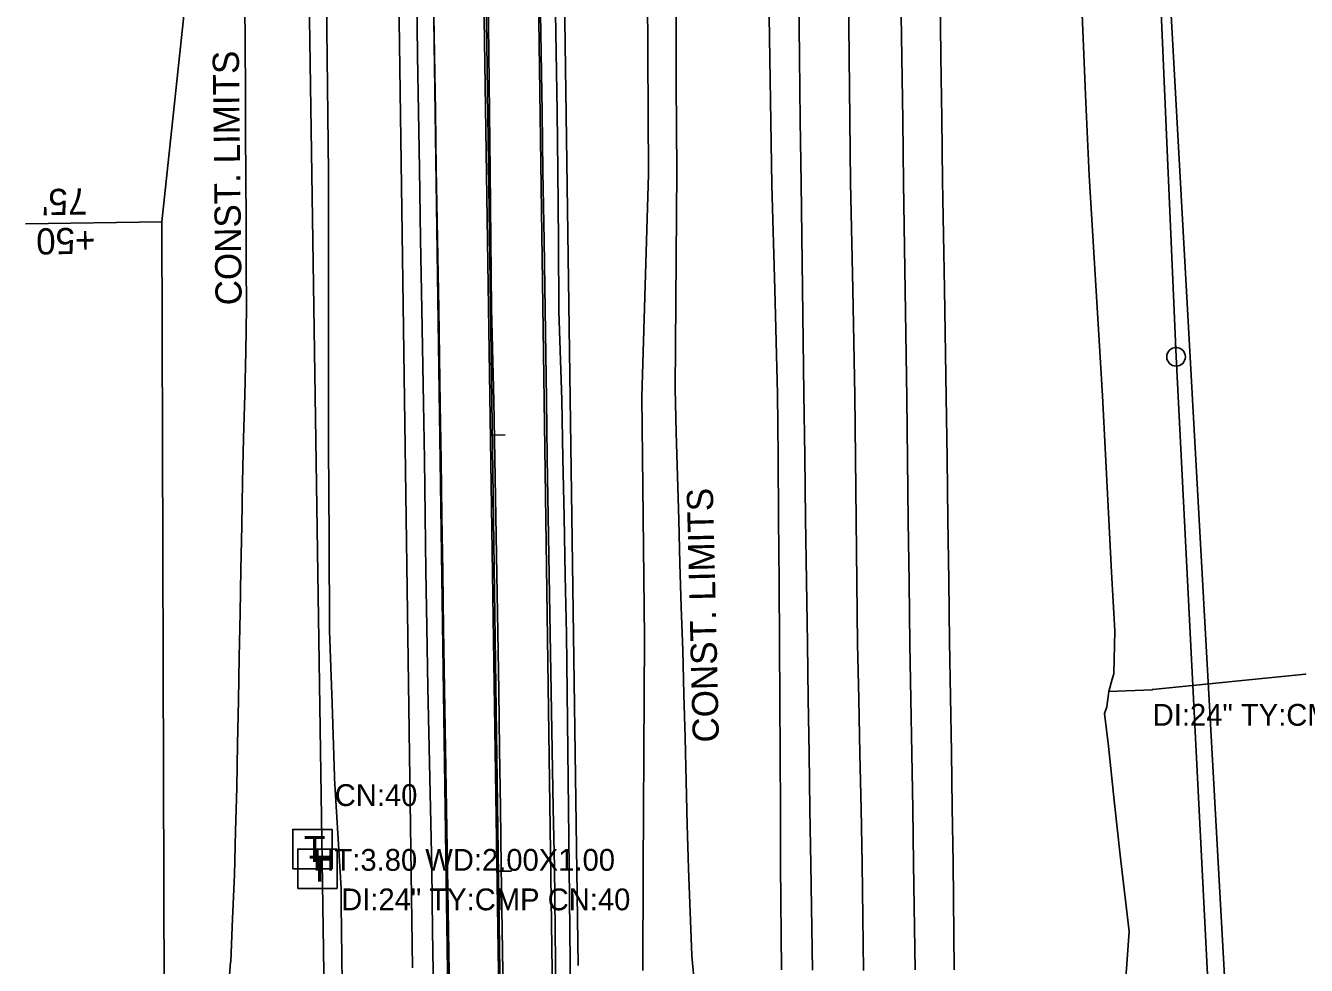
# Model space of a CAD drawing. Extents: x 1674300 to 1677920, y 225056 to 231852.
# Drawn here: x 1677262.1 to 1677555.6, y 229456.1 to 229671.6 of the extents above; entities that cross this region are included whole.
import ezdxf

# ---------------------------------------------------------------- set-up
doc = ezdxf.new("R2010")
doc.units = 0
for name, color, linetype in [('R_Annotation', 7, 'Continuous'), ('R_Horz Alg', 7, 'Continuous'), ('R_Horz Alg Annot', 7, 'Continuous'), ('R_Proposed Const Limits_Cut', 7, 'Continuous'), ('R_Proposed Const Limits_Fill', 7, 'Continuous'), ('R_Proposed Road_Lane', 7, 'Continuous'), ('R_Proposed Road_Shoulder', 7, 'Continuous'), ('R_ROW', 7, 'Continuous'), ('R_ROW Annot', 7, 'Continuous'), ('S_DITCHLINE', 7, 'Continuous'), ('S_DRG_PT_SYM', 7, 'Continuous'), ('S_EDGE_PAVEMENT', 7, 'Continuous'), ('S_ELECTRIC_UTILITIES', 7, 'Continuous'), ('S_EXIST_ROW', 7, 'Continuous'), ('S_EXISTING_ALIGNMENT', 7, 'Continuous'), ('S_PAVEMENT_CROWN', 7, 'Continuous'), ('S_SHOULDER', 7, 'Continuous'), ('S_SIDE_DRAIN', 7, 'Continuous'), ('S_SIDE_DRAIN_ANNOT', 7, 'Continuous'), ('S_TELEPHONE_UTILITIES', 7, 'Continuous'), ('S_TELEPHONE_UTILITIES_ANNOT', 7, 'Continuous'), ('S_UTILITY_POLE', 7, 'Continuous'), ('S_UTL_PT_SYM', 7, 'Continuous')]:
    doc.layers.add(name, color=color, linetype=linetype)

msp = doc.modelspace()

# ---------------------------------------------------------------- linework, layer by layer
at = {"layer": 'R_Horz Alg'}
msp.add_line((1677377.01, 229008.91), (1677360.58, 230177.65), dxfattribs=at)
at = {"layer": 'R_Horz Alg Annot'}
for points in [[(1677372.02, 229577.75), (1677369.02, 229577.71)], [(1677373.42, 229477.76), (1677370.42, 229477.72)]]:
    msp.add_lwpolyline(points, dxfattribs=at)
at = {"layer": 'R_Proposed Const Limits_Cut'}
msp.add_lwpolyline([(1677308.24, 229446.84), (1677309.07, 229456.86), (1677309.08, 229457.01), (1677309.52, 229466.86), (1677309.96, 229476.87), (1677310.21, 229486.88), (1677310.45, 229496.88), (1677310.66, 229506.88), (1677310.85, 229516.89), (1677311.03, 229526.89), (1677311.22, 229536.9), (1677311.43, 229546.9), (1677311.65, 229556.9), (1677311.82, 229566.91), (1677312.04, 229576.91), (1677312.3, 229586.92), (1677312.52, 229596.92), (1677312.7, 229606.92), (1677312.66, 229616.92), (1677312.6, 229626.92), (1677312.54, 229636.92), (1677312.5, 229646.92), (1677312.44, 229656.92), (1677312.36, 229666.92), (1677312.35, 229676.93)], dxfattribs=at)
at = {"layer": 'R_Proposed Const Limits_Fill'}
msp.add_lwpolyline([(1677415.72, 229448.36), (1677414.81, 229458.34), (1677414.79, 229458.49), (1677414.36, 229468.34), (1677414, 229478.33), (1677413.69, 229488.33), (1677413.49, 229498.33), (1677413.23, 229508.33), (1677412.94, 229518.32), (1677412.71, 229528.32), (1677412.35, 229538.32), (1677412.03, 229548.31), (1677411.76, 229558.31), (1677411.46, 229568.31), (1677411.18, 229578.3), (1677410.99, 229588.3), (1677411.04, 229598.3), (1677411.08, 229608.31), (1677411.17, 229618.31), (1677411.24, 229628.31), (1677411.31, 229638.31), (1677411.25, 229648.31), (1677411.21, 229658.31), (1677411.19, 229668.31), (1677411.16, 229678.31)], dxfattribs=at)
at = {"layer": 'R_Proposed Road_Lane'}
for p, q in [((1677362.08, 229217.16), (1677355.47, 229687.53)), ((1677386.08, 229217.34), (1677379.47, 229687.87))]:
    msp.add_line(p, q, dxfattribs=at)
at = {"layer": 'R_Proposed Road_Shoulder'}
for p, q in [((1677350.73, 229455.59), (1677347.47, 229687.42)), ((1677388.73, 229456.13), (1677385.47, 229687.95))]:
    msp.add_line(p, q, dxfattribs=at)
at = {"layer": 'R_ROW'}
for p, q in [((1677293.32, 229626.65), (1677323.6, 229911.16)), ((1677294.58, 229181.63), (1677293.32, 229626.65))]:
    msp.add_line(p, q, dxfattribs=at)
at = {"layer": 'R_ROW Annot'}
msp.add_line((1677293.32, 229626.65), (1677262.08, 229626.13), dxfattribs=at)
at = {"layer": 'S_DITCHLINE'}
for points in [[(1677332.94, 229497.27), (1677332.9, 229499.42), (1677332.33, 229516.14), (1677331.76, 229532.86), (1677331.63, 229554.02), (1677331.51, 229575.18), (1677331.5, 229590.35), (1677331.5, 229605.52), (1677331.51, 229621.71), (1677331.52, 229637.89), (1677331.37, 229651.06), (1677331.21, 229664.23), (1677331.06, 229677.4)], [(1677403.55, 229454.93), (1677403.6, 229478.23), (1677403.68, 229491.49), (1677403.77, 229504.75), (1677403.86, 229518.01), (1677403.95, 229531.26), (1677403.8, 229545.08), (1677403.64, 229558.9), (1677403.48, 229572.71), (1677403.33, 229586.53), (1677403.71, 229599.28), (1677404.09, 229612.04), (1677404.47, 229624.8), (1677404.85, 229637.56), (1677404.78, 229651.36), (1677404.72, 229665.16), (1677404.65, 229678.97)], [(1677513.78, 229446.92), (1677515.05, 229463.87), (1677512.97, 229481.43), (1677511.61, 229493.9), (1677510.26, 229506.37), (1677509.37, 229513.91), (1677509.86, 229515.44), (1677510.34, 229518.94), (1677511.09, 229521.77), (1677511.46, 229522.98), (1677511.69, 229532.84), (1677510.98, 229546.32), (1677510.28, 229559.79), (1677509.58, 229573.27), (1677508.88, 229586.74), (1677508.12, 229599.38), (1677507.36, 229612.01), (1677506.6, 229624.64), (1677505.84, 229637.27), (1677505.04, 229655.77), (1677504.24, 229674.27)], [(1677510.34, 229518.94), (1677520.35, 229519.32)], [(1677339.09, 229147.6), (1677337.05, 229154.23), (1677340.76, 229158.8), (1677340.29, 229166.32), (1677337.9, 229173.01), (1677337.54, 229184.7), (1677337.47, 229206.29), (1677336.46, 229228.55), (1677335.46, 229250.81), (1677335.75, 229270.19), (1677336.05, 229289.58), (1677334.99, 229313.98), (1677333.93, 229338.37), (1677333.99, 229360.23), (1677334.04, 229382.08), (1677334.5, 229402.19), (1677334.96, 229422.29), (1677334.69, 229446.15), (1677334.41, 229470.02), (1677334.41, 229473.73)]]:
    msp.add_lwpolyline(points, dxfattribs=at)
at = {"layer": 'S_DRG_PT_SYM'}
for points in [[(1677555.42, 229522.92), (1677555.42, 229522.97), (1677555.42, 229522.92), (1677555.37, 229522.92), (1677555.42, 229522.92), (1677555.42, 229522.87), (1677555.42, 229522.92), (1677555.47, 229522.92)], [(1677520.36, 229519.36), (1677520.36, 229519.41), (1677520.36, 229519.36), (1677520.31, 229519.36), (1677520.36, 229519.36), (1677520.36, 229519.31), (1677520.36, 229519.36), (1677520.41, 229519.36)], [(1677332.92, 229497.67), (1677332.92, 229497.72), (1677332.92, 229497.67), (1677332.87, 229497.67), (1677332.92, 229497.67), (1677332.92, 229497.62), (1677332.92, 229497.67), (1677332.97, 229497.67)], [(1677334.4, 229473.76), (1677334.4, 229473.81), (1677334.4, 229473.76), (1677334.35, 229473.76), (1677334.4, 229473.76), (1677334.4, 229473.71), (1677334.4, 229473.76), (1677334.45, 229473.76)]]:
    msp.add_lwpolyline(points, dxfattribs=at)
at = {"layer": 'S_EDGE_PAVEMENT'}
for points in [[(1677359.23, 229449.72), (1677359, 229463.99), (1677358.76, 229478.26), (1677358.53, 229492.04), (1677358.31, 229505.82), (1677358.08, 229519.61), (1677357.86, 229533.39), (1677357.67, 229546.25), (1677357.48, 229559.11), (1677357.29, 229571.97), (1677357.1, 229584.84), (1677356.8, 229606.58), (1677356.5, 229622.72), (1677356.2, 229638.87), (1677355.99, 229651.98), (1677355.78, 229665.09), (1677355.57, 229678.21)], [(1677383.6, 229449.7), (1677383.44, 229464.22), (1677383.27, 229478.73), (1677383.02, 229492.11), (1677382.77, 229505.49), (1677382.53, 229518.87), (1677382.28, 229532.25), (1677382.06, 229545.67), (1677381.85, 229559.1), (1677381.64, 229572.52), (1677381.43, 229585.94), (1677381.14, 229606.46), (1677380.9, 229622.33), (1677380.66, 229638.21), (1677380.45, 229651.8), (1677380.24, 229665.39), (1677380.02, 229678.98)], [(1677442.45, 229455.05), (1677442.04, 229479.26), (1677441.85, 229491.93), (1677441.66, 229504.6), (1677441.47, 229517.27), (1677441.27, 229529.94), (1677441.07, 229544.26), (1677440.86, 229558.58), (1677440.65, 229572.9), (1677440.45, 229587.22), (1677440.13, 229611.36), (1677439.8, 229635.51), (1677439.64, 229649.9), (1677439.48, 229664.28), (1677439.31, 229678.67)], [(1677465.93, 229455.12), (1677465.6, 229479.4), (1677465.39, 229492), (1677465.18, 229504.6), (1677464.97, 229517.2), (1677464.76, 229529.8), (1677464.57, 229543.9), (1677464.39, 229558), (1677464.2, 229572.09), (1677464.02, 229586.19), (1677463.66, 229610.86), (1677463.3, 229635.53), (1677463.1, 229649.96), (1677462.89, 229664.39), (1677462.69, 229678.82)]]:
    msp.add_lwpolyline(points, dxfattribs=at)
at = {"layer": 'S_ELECTRIC_UTILITIES'}
for p, q in [((1677525.77, 229595.69), (1677514.95, 229844)), ((1677537.26, 229370.07), (1677525.77, 229595.69))]:
    msp.add_line(p, q, dxfattribs=at)
at = {"layer": 'S_EXIST_ROW'}
for p, q in [((1677337.07, 229010.49), (1677299.88, 231497.46)), ((1677555.5, 229117.02), (1677521.25, 229735.57))]:
    msp.add_line(p, q, dxfattribs=at)
at = {"layer": 'S_EXISTING_ALIGNMENT'}
msp.add_line((1677375.22, 229134.43), (1677343.44, 231259.98), dxfattribs=at)
at = {"layer": 'S_PAVEMENT_CROWN'}
for points in [[(1677371.51, 229449.83), (1677371.31, 229464.31), (1677371.11, 229478.79), (1677370.91, 229492.23), (1677370.72, 229505.67), (1677370.53, 229519.11), (1677370.33, 229532.55), (1677370.11, 229545.8), (1677369.88, 229559.05), (1677369.65, 229572.31), (1677369.42, 229585.56), (1677368.88, 229606.73), (1677368.73, 229622.48), (1677368.58, 229638.23), (1677368.43, 229651.74), (1677368.27, 229665.24), (1677368.12, 229678.74)], [(1677454.11, 229454.96), (1677453.84, 229479.45), (1677453.56, 229492.05), (1677453.29, 229504.65), (1677453.02, 229517.26), (1677452.75, 229529.86), (1677452.6, 229544.09), (1677452.44, 229558.31), (1677452.29, 229572.54), (1677452.14, 229586.76), (1677451.64, 229611.2), (1677451.15, 229635.63), (1677451, 229650.06), (1677450.85, 229664.49), (1677450.7, 229678.91)]]:
    msp.add_lwpolyline(points, dxfattribs=at)
at = {"layer": 'S_SHOULDER'}
for points in [[(1677355.56, 229449.95), (1677355.36, 229464.12), (1677355.16, 229478.29), (1677354.87, 229492.15), (1677354.58, 229506.01), (1677354.29, 229519.86), (1677354, 229533.72), (1677353.83, 229546.52), (1677353.65, 229559.33), (1677353.48, 229572.13), (1677353.3, 229584.93), (1677352.89, 229606.52), (1677352.61, 229622.65), (1677352.33, 229638.78), (1677352.13, 229651.82), (1677351.93, 229664.86), (1677351.74, 229677.91)], [(1677386.96, 229449.67), (1677386.8, 229464.17), (1677386.64, 229478.67), (1677386.49, 229492.03), (1677386.35, 229505.38), (1677386.2, 229518.74), (1677386.06, 229532.1), (1677385.78, 229545.52), (1677385.5, 229558.94), (1677385.22, 229572.36), (1677384.94, 229585.78), (1677384.31, 229606.18), (1677384.2, 229622.26), (1677384.09, 229638.33), (1677383.88, 229651.92), (1677383.67, 229665.5), (1677383.46, 229679.08)], [(1677435.32, 229455.13), (1677435.12, 229479.1), (1677435.06, 229491.75), (1677435, 229504.41), (1677434.94, 229517.06), (1677434.87, 229529.71), (1677434.76, 229544.08), (1677434.64, 229558.44), (1677434.53, 229572.8), (1677434.41, 229587.16), (1677433.76, 229611.13), (1677433.1, 229635.09), (1677432.88, 229649.58), (1677432.65, 229664.07), (1677432.43, 229678.56)], [(1677474.9, 229455.1), (1677474.67, 229479.64), (1677474.47, 229492.32), (1677474.27, 229505.01), (1677474.07, 229517.7), (1677473.87, 229530.38), (1677473.68, 229544.39), (1677473.48, 229558.39), (1677473.29, 229572.39), (1677473.09, 229586.4), (1677472.67, 229611.22), (1677472.24, 229636.04), (1677472.05, 229650.3), (1677471.85, 229664.55), (1677471.66, 229678.81)]]:
    msp.add_lwpolyline(points, dxfattribs=at)
at = {"layer": 'S_SIDE_DRAIN'}
for p, q in [((1677520.36, 229519.36), (1677555.42, 229522.92)), ((1677334.4, 229473.76), (1677332.92, 229497.67))]:
    msp.add_line(p, q, dxfattribs=at)
at = {"layer": 'S_TELEPHONE_UTILITIES'}
for points in [[(1677323.31, 229478.3), (1677323.31, 229487.3), (1677332.31, 229487.3), (1677332.31, 229478.3)], [(1677324.45, 229473.79), (1677324.45, 229482.79), (1677333.45, 229482.79), (1677333.45, 229473.79)]]:
    msp.add_lwpolyline(points, close=True, dxfattribs=at)
at = {"layer": 'S_UTILITY_POLE'}
msp.add_line((1677525.64, 229597.81), (1677525.64, 229599.92), dxfattribs=at)
msp.add_circle((1677525.77, 229595.67), 2.13, dxfattribs=at)
at = {"layer": 'S_UTL_PT_SYM'}
msp.add_lwpolyline([(1677525.77, 229595.69), (1677525.77, 229595.74), (1677525.77, 229595.69), (1677525.72, 229595.69), (1677525.77, 229595.69), (1677525.77, 229595.64), (1677525.77, 229595.69), (1677525.82, 229595.69)], dxfattribs=at)

# ---------------------------------------------------------------- texts
at = {"layer": 'R_Annotation'}
for rotation, p in [(90.6576, (1677311.61, 229607.5)), (91.3951, (1677421.01, 229507.29))]:
    msp.add_text('CONST. LIMITS', height=6, rotation=rotation, dxfattribs=at).set_placement(p)
at = {"layer": 'R_ROW Annot'}
for s, p in [("75'", (1677276.18, 229634.3)), ('+50', (1677278.05, 229625.33))]:
    msp.add_text(s, height=6, rotation=180.9497, dxfattribs=at).set_placement(p)
at = {"layer": 'S_SIDE_DRAIN_ANNOT'}
for s, p in [('DI:24" TY:CMP CN:10 BOTTOM RUSTED OUT', (1677520.41, 229511.07)), ('CN:40', (1677332.92, 229492.67)), ('DI:24" TY:CMP CN:40', (1677334.4, 229468.76))]:
    msp.add_text(s, height=5, dxfattribs=at).set_placement(p)
at = {"layer": 'S_TELEPHONE_UTILITIES'}
for p in [(1677325.87, 229479.8), (1677327.01, 229475.29)]:
    msp.add_text('T', height=6, rotation=360, dxfattribs=at).set_placement(p)
at = {"layer": 'S_TELEPHONE_UTILITIES_ANNOT'}
msp.add_text('HT:3.80 WD:2.00X1.00', height=5, dxfattribs=at).set_placement((1677328.04, 229477.82))

doc.saveas('drawing.dxf')
